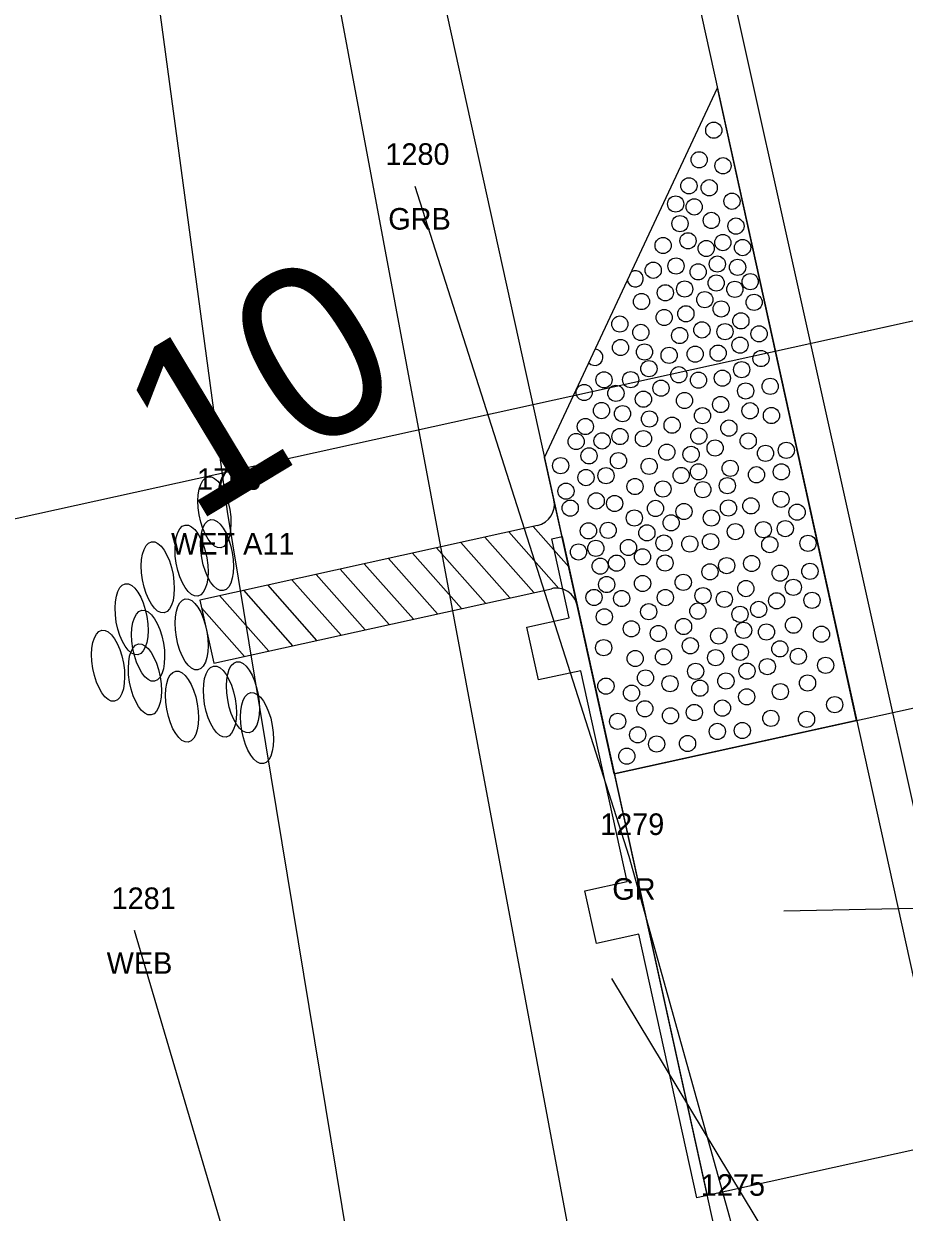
# Model space of a CAD drawing. Extents: x 2522090 to 2524658, y 882711 to 887512.
# Drawn here: x 2523721.1 to 2523761.9, y 885177.3 to 885232.4 of the extents above; entities that cross this region are included whole.
import ezdxf

# ---------------------------------------------------------------- set-up
doc = ezdxf.new("R2010")
doc.units = 0
for name, color, linetype in [('RD_EV_JurisArea', 7, 'Continuous'), ('RD_EX_GuardRail', 7, 'Continuous'), ('RD_EX_GuardRail_txCode', 7, 'Continuous'), ('RD_EX_H2O', 7, 'Continuous'), ('RD_EX_H2O_txCode', 7, 'Continuous'), ('RD_EX_H2O_WetLd_txCode', 7, 'Continuous'), ('RD_EX_Road', 7, 'Continuous'), ('RD_EX_VEG', 7, 'Continuous'), ('RD_HC_Data_Tic', 7, 'Continuous'), ('RD_HC_TX_Sta50', 7, 'Continuous'), ('RD_PD_Bridge', 7, 'Continuous'), ('RD_PD_Final_TrvlWay', 7, 'Continuous'), ('RD_PD_GR', 7, 'Continuous'), ('RD_PD_PatLn5', 7, 'Continuous'), ('RD_PD_PatLn6', 7, 'Continuous'), ('RD_PD_PaveShd', 7, 'Continuous'), ('RD_SMD_Locator', 7, 'Continuous')]:
    doc.layers.add(name, color=color, linetype=linetype)

# ---------------------------------------------------------------- blocks, each defined once
blk = doc.blocks.new('TBC1')
at = {"layer": 'RD_PD_GR'}
blk.add_lwpolyline([(12.5, 2.5), (15, 2.5), (15, 0.492), (25, 0.492), (25, 2.5), (27.5, 2.5), (27.5, 0.492), (31.25, 0.492), (31.25, 0), (0, 0), (0, 0.492), (12.5, 0.492)], close=True, dxfattribs=at)

msp = doc.modelspace()

# ---------------------------------------------------------------- linework, layer by layer
at = {"layer": 'RD_EV_JurisArea'}
msp.add_lwpolyline([(2523761.167, 885134.03), (2523740.577, 885149.032), (2523730.546, 885209.774), (2523710.597, 885357.475), (2523698.092, 885411.187), (2523674.928, 885498.624), (2523657.597, 885564.237), (2523640.817, 885610.871), (2523583.661, 885726.913), (2523539.208, 885693.17), (2523494.424, 885646.975)], dxfattribs=at)
at = {"layer": 'RD_EX_GuardRail'}
msp.add_lwpolyline([(2523760.648, 885150.236), (2523753.83, 885177.075), (2523749.161, 885193.784), (2523739.251, 885224.823)], dxfattribs=at)
at = {"layer": 'RD_EX_H2O'}
msp.add_line((2523738.909, 885147.498), (2523726.241, 885190.354), dxfattribs=at)
at = {"layer": 'RD_EX_Road'}
msp.add_line((2523771.576, 885154.562), (2523750.317, 885250.176), dxfattribs=at)
at = {"layer": 'RD_EX_VEG'}
msp.add_lwpolyline([(2523749.808, 885158.06), (2523732.862, 885248.57), (2523691.618, 885438.948), (2523639.516, 885601.035)], dxfattribs=at)
at = {"layer": 'RD_HC_Data_Tic'}
msp.add_line((2523767.659, 885219.76), (2523759.846, 885218.04), dxfattribs=at)
at = {"layer": 'RD_PD_Bridge'}
msp.add_line((2523748.471, 885197.618), (2523794.372, 885207.726), dxfattribs=at)
for points in [[(2523748.471, 885197.618), (2523785.03, 885031.596)], [(2523798.673, 885188.194), (2523752.772, 885178.086)]]:
    msp.add_lwpolyline(points, dxfattribs=at)
at = {"layer": 'RD_PD_Final_TrvlWay'}
msp.add_line((2523698.951, 885475.979), (2524014, 884045.256), dxfattribs=at)
at = {"layer": 'RD_PD_GR'}
msp.add_line((2523746.052, 885208.605), (2523684.387, 885488.643), dxfattribs=at)
at = {"layer": 'RD_PD_PatLn5'}
msp.add_line((2523845.787, 885236.964), (2523689.531, 885202.556), dxfattribs=at)
at = {"layer": 'RD_PD_PatLn6'}
for p, q in [((2523756.322, 885191.277), (2523916.292, 885194.412)), ((2523748.348, 885188.144), (2523831.037, 885051.167))]:
    msp.add_line(p, q, dxfattribs=at)
at = {"layer": 'RD_PD_PaveShd'}
for p, q in [((2523745.246, 885212.267), (2523753.251, 885229.39)), ((2523759.702, 885200.091), (2523753.251, 885229.39)), ((2523745.891, 885209.338), (2523745.246, 885212.267)), ((2523746.536, 885206.408), (2523745.891, 885209.338)), ((2523744.915, 885209.122), (2523729.268, 885205.668)), ((2523745.91, 885206.206), (2523743.589, 885208.829)), ((2523746.36, 885207.207), (2523744.706, 885209.076)), ((2523743.629, 885205.766), (2523741.355, 885208.336)), ((2523743.629, 885205.766), (2523741.355, 885208.336)), ((2523744.746, 885206.013), (2523742.472, 885208.583)), ((2523744.746, 885206.013), (2523742.472, 885208.583)), ((2523741.395, 885205.273), (2523739.121, 885207.843)), ((2523741.395, 885205.273), (2523739.121, 885207.843)), ((2523742.512, 885205.519), (2523740.238, 885208.09)), ((2523742.512, 885205.519), (2523740.238, 885208.09)), ((2523738.044, 885204.533), (2523735.77, 885207.103)), ((2523738.044, 885204.533), (2523735.77, 885207.103)), ((2523739.161, 885204.78), (2523736.887, 885207.35)), ((2523739.161, 885204.78), (2523736.887, 885207.35)), ((2523740.278, 885205.026), (2523738.004, 885207.597)), ((2523740.278, 885205.026), (2523738.004, 885207.597)), ((2523746.322, 885207.379), (2523746.322, 885207.379)), ((2523735.81, 885204.04), (2523733.536, 885206.61)), ((2523735.81, 885204.04), (2523733.536, 885206.61)), ((2523736.927, 885204.287), (2523734.653, 885206.857)), ((2523736.927, 885204.287), (2523734.653, 885206.857)), ((2523729.915, 885202.739), (2523745.559, 885206.192)), ((2523733.576, 885203.547), (2523731.302, 885206.117)), ((2523733.576, 885203.547), (2523731.302, 885206.117)), ((2523734.693, 885203.793), (2523732.419, 885206.364)), ((2523734.693, 885203.793), (2523732.419, 885206.364)), ((2523746.536, 885206.408), (2523748.471, 885197.618)), ((2523748.471, 885197.618), (2523746.536, 885206.408)), ((2523729.268, 885205.668), (2523729.915, 885202.739)), ((2523729.268, 885205.668), (2523729.915, 885202.739)), ((2523732.459, 885203.3), (2523730.185, 885205.871)), ((2523732.459, 885203.3), (2523730.185, 885205.871)), ((2523731.342, 885203.054), (2523729.348, 885205.307)), ((2523731.342, 885203.054), (2523729.348, 885205.307)), ((2523759.702, 885200.091), (2523748.471, 885197.618))]:
    msp.add_line(p, q, dxfattribs=at)
for centre in [(2523753.083, 885227.427), (2523753.083, 885227.427), (2523752.405, 885226.058), (2523752.405, 885226.058), (2523753.511, 885225.782), (2523753.511, 885225.782), (2523751.931, 885224.852), (2523751.931, 885224.852), (2523752.872, 885224.763), (2523752.872, 885224.763), (2523751.317, 885224.011), (2523752.176, 885223.875), (2523752.176, 885223.875), (2523753.924, 885224.137), (2523753.924, 885224.137), (2523752.971, 885223.25), (2523752.971, 885223.25), (2523751.517, 885223.101), (2523754.11, 885222.987), (2523754.11, 885222.987), (2523751.887, 885222.306), (2523751.887, 885222.306), (2523753.502, 885222.223), (2523753.502, 885222.223), (2523750.735, 885222.088), (2523750.735, 885222.088), (2523752.732, 885221.95), (2523752.732, 885221.95), (2523754.418, 885221.991), (2523754.418, 885221.991), (2523751.334, 885221.137), (2523751.334, 885221.137), (2523753.249, 885221.228), (2523753.249, 885221.228), (2523754.186, 885221.075), (2523754.186, 885221.075), (2523750.277, 885220.942), (2523750.277, 885220.942), (2523752.36, 885220.866), (2523752.36, 885220.866), (2523751.734, 885220.071), (2523751.734, 885220.071), (2523753.195, 885220.35), (2523753.195, 885220.35), (2523754.059, 885220.057), (2523754.059, 885220.057), (2523754.771, 885220.414), (2523754.771, 885220.414), (2523749.734, 885219.491), (2523749.734, 885219.491), (2523750.839, 885219.898), (2523750.839, 885219.898), (2523752.667, 885219.581), (2523752.667, 885219.581), (2523754.953, 885219.457), (2523754.953, 885219.457), (2523751.79, 885218.926), (2523751.79, 885218.926), (2523753.426, 885219.149), (2523753.426, 885219.149), (2523748.73, 885218.449), (2523750.784, 885218.753), (2523750.784, 885218.753), (2523754.339, 885218.596), (2523754.339, 885218.596), (2523749.703, 885218.062), (2523749.703, 885218.062), (2523751.504, 885217.917), (2523751.504, 885217.917), (2523752.533, 885218.178), (2523752.533, 885218.178), (2523753.603, 885218.096), (2523753.603, 885218.096), (2523755.182, 885217.997), (2523755.182, 885217.997), (2523748.762, 885217.362), (2523748.762, 885217.362), (2523754.3, 885217.473), (2523754.3, 885217.473), (2523749.872, 885217.154), (2523749.872, 885217.154), (2523751.013, 885217), (2523751.013, 885217), (2523752.221, 885217.056), (2523752.221, 885217.056), (2523753.283, 885217.103), (2523753.283, 885217.103), (2523755.271, 885216.851), (2523755.271, 885216.851), (2523750.077, 885216.383), (2523750.077, 885216.383), (2523751.464, 885216.102), (2523751.464, 885216.102), (2523754.376, 885216.338), (2523754.376, 885216.338), (2523747.996, 885215.865), (2523747.996, 885215.865), (2523749.232, 885215.874), (2523749.232, 885215.874), (2523752.374, 885215.85), (2523752.374, 885215.85), (2523753.482, 885215.944), (2523753.482, 885215.944), (2523755.697, 885215.563), (2523755.697, 885215.563), (2523747.077, 885215.279), (2523748.548, 885215.242), (2523748.548, 885215.242), (2523749.822, 885214.968), (2523749.822, 885214.968), (2523750.639, 885215.479), (2523750.639, 885215.479), (2523754.561, 885215.351), (2523754.561, 885215.351), (2523747.881, 885214.441), (2523747.881, 885214.441), (2523751.727, 885214.908), (2523751.727, 885214.908), (2523753.4, 885214.721), (2523753.4, 885214.721), (2523754.765, 885214.434), (2523754.765, 885214.434), (2523748.855, 885214.298), (2523748.855, 885214.298), (2523750.103, 885214.053), (2523750.103, 885214.053), (2523752.561, 885214.204), (2523752.561, 885214.204), (2523755.755, 885214.212), (2523755.755, 885214.212), (2523747.134, 885213.702), (2523747.134, 885213.702), (2523751.152, 885213.764), (2523751.152, 885213.764), (2523753.783, 885213.631), (2523753.783, 885213.631), (2523746.705, 885213.009), (2523747.907, 885213.037), (2523747.907, 885213.037), (2523748.734, 885213.239), (2523748.734, 885213.239), (2523749.823, 885213.144), (2523749.823, 885213.144), (2523752.391, 885213.261), (2523752.391, 885213.261), (2523754.679, 885213.036), (2523754.679, 885213.036), (2523747.304, 885212.344), (2523747.304, 885212.344), (2523747.304, 885212.344), (2523750.907, 885212.517), (2523750.907, 885212.517), (2523752.031, 885212.413), (2523752.031, 885212.413), (2523753.144, 885212.71), (2523753.144, 885212.71), (2523755.479, 885212.461), (2523755.479, 885212.461), (2523756.442, 885212.599), (2523756.442, 885212.599), (2523745.985, 885211.892), (2523745.985, 885211.892), (2523748.665, 885212.121), (2523748.665, 885212.121), (2523750.088, 885211.858), (2523750.088, 885211.858), (2523753.844, 885211.769), (2523753.844, 885211.769), (2523747.159, 885211.339), (2523747.159, 885211.339), (2523748.09, 885211.426), (2523748.09, 885211.426), (2523751.571, 885211.438), (2523751.571, 885211.438), (2523752.374, 885211.606), (2523752.374, 885211.606), (2523755.061, 885211.47), (2523755.061, 885211.47), (2523756.213, 885211.603), (2523756.213, 885211.603), (2523746.232, 885210.709), (2523746.232, 885210.709), (2523749.434, 885210.923), (2523749.434, 885210.923), (2523750.726, 885210.809), (2523750.726, 885210.809), (2523752.576, 885210.78), (2523752.576, 885210.78), (2523753.711, 885210.963), (2523753.711, 885210.963), (2523747.636, 885210.258), (2523747.636, 885210.258), (2523748.488, 885210.139), (2523748.488, 885210.139), (2523754.804, 885210.027), (2523754.804, 885210.027), (2523756.198, 885210.334), (2523756.198, 885210.334), (2523746.431, 885209.925), (2523746.431, 885209.925), (2523749.401, 885209.466), (2523749.401, 885209.466), (2523750.383, 885209.911), (2523750.383, 885209.911), (2523751.7, 885209.768), (2523751.7, 885209.768), (2523752.973, 885209.465), (2523752.973, 885209.465), (2523753.762, 885209.928), (2523753.762, 885209.928), (2523756.943, 885209.736), (2523751.107, 885209.243), (2523751.107, 885209.243), (2523755.382, 885208.925), (2523755.382, 885208.925), (2523756.396, 885208.975), (2523756.396, 885208.975), (2523747.274, 885208.869), (2523747.274, 885208.869), (2523748.187, 885208.895), (2523748.187, 885208.895), (2523749.984, 885208.778), (2523749.984, 885208.778), (2523752.935, 885208.373), (2523752.935, 885208.373), (2523754.086, 885208.836), (2523754.086, 885208.836), (2523746.815, 885207.894), (2523746.815, 885207.894), (2523747.618, 885208.062), (2523747.618, 885208.062), (2523749.128, 885208.101), (2523749.128, 885208.101), (2523750.774, 885208.306), (2523750.774, 885208.306), (2523751.973, 885208.264), (2523751.973, 885208.264), (2523755.677, 885208.234), (2523755.677, 885208.234), (2523757.449, 885208.294), (2523757.449, 885208.294), (2523748.579, 885207.377), (2523748.579, 885207.377), (2523749.781, 885207.665), (2523749.781, 885207.665), (2523750.825, 885207.38), (2523750.825, 885207.38), (2523753.681, 885207.261), (2523753.681, 885207.261), (2523754.837, 885207.359), (2523754.837, 885207.359), (2523747.82, 885207.236), (2523747.82, 885207.236), (2523752.905, 885206.972), (2523752.905, 885206.972), (2523756.158, 885206.913), (2523756.158, 885206.913), (2523757.538, 885206.997), (2523757.538, 885206.997), (2523748.12, 885206.384), (2523749.784, 885206.434), (2523749.784, 885206.434), (2523751.668, 885206.487), (2523751.668, 885206.487), (2523754.57, 885206.197), (2523754.57, 885206.197), (2523756.768, 885206.256), (2523756.768, 885206.256), (2523747.535, 885205.787), (2523747.535, 885205.787), (2523748.815, 885205.735), (2523748.815, 885205.735), (2523750.839, 885205.78), (2523750.839, 885205.78), (2523752.585, 885205.869), (2523752.585, 885205.869), (2523753.571, 885205.701), (2523753.571, 885205.701), (2523755.995, 885205.633), (2523755.995, 885205.633), (2523757.635, 885205.655), (2523757.635, 885205.655), (2523750.069, 885205.126), (2523750.069, 885205.126), (2523752.345, 885205.155), (2523752.345, 885205.155), (2523755.162, 885205.232), (2523755.162, 885205.232), (2523748.013, 885204.888), (2523748.013, 885204.888), (2523754.3, 885205.007), (2523754.3, 885205.007), (2523749.263, 885204.333), (2523749.263, 885204.333), (2523750.513, 885204.116), (2523750.513, 885204.116), (2523751.683, 885204.438), (2523751.683, 885204.438), (2523753.313, 885204.001), (2523753.313, 885204.001), (2523754.464, 885204.264), (2523755.524, 885204.185), (2523755.524, 885204.185), (2523756.778, 885204.501), (2523756.778, 885204.501), (2523758.072, 885204.085), (2523758.072, 885204.085), (2523747.982, 885203.459), (2523747.982, 885203.459), (2523751.994, 885203.549), (2523751.994, 885203.549), (2523749.442, 885202.958), (2523749.442, 885202.958), (2523750.755, 885203.035), (2523750.755, 885203.035), (2523753.168, 885202.996), (2523753.168, 885202.996), (2523754.316, 885203.249), (2523754.316, 885203.249), (2523756.145, 885203.404), (2523756.145, 885203.404), (2523756.999, 885203.057), (2523756.999, 885203.057), (2523752.241, 885202.366), (2523752.241, 885202.366), (2523754.622, 885202.375), (2523754.622, 885202.375), (2523755.566, 885202.583), (2523755.566, 885202.583), (2523758.265, 885202.642), (2523758.265, 885202.642), (2523749.92, 885202.059), (2523749.92, 885202.059), (2523751.055, 885201.793), (2523751.055, 885201.793), (2523753.645, 885201.915), (2523753.645, 885201.915), (2523757.429, 885201.824), (2523757.429, 885201.824), (2523748.085, 885201.68), (2523748.085, 885201.68), (2523749.272, 885201.355), (2523749.272, 885201.355), (2523752.44, 885201.582), (2523752.44, 885201.582), (2523756.169, 885201.424), (2523756.169, 885201.424), (2523753.484, 885200.662), (2523753.484, 885200.662), (2523754.61, 885201.183), (2523754.61, 885201.183), (2523758.687, 885200.821), (2523758.687, 885200.821), (2523749.889, 885200.63), (2523749.889, 885200.63), (2523751.076, 885200.305), (2523751.076, 885200.305), (2523752.18, 885200.461), (2523752.18, 885200.461), (2523755.728, 885200.188), (2523755.728, 885200.188), (2523757.382, 885200.143), (2523757.382, 885200.143), (2523748.63, 885200.047), (2523748.63, 885200.047), (2523753.249, 885199.582), (2523753.249, 885199.582), (2523754.403, 885199.624), (2523754.403, 885199.624), (2523749.557, 885199.423), (2523751.868, 885199.022), (2523751.868, 885199.022), (2523750.434, 885198.997), (2523750.434, 885198.997), (2523750.434, 885198.997), (2523749.053, 885198.436), (2523749.053, 885198.436)]:
    msp.add_circle(centre, 0.375, dxfattribs=at)
for centre, radius, start, end in [((2523749.446, 885220.543), 0.375, 191.7998, 118.0848), ((2523747.57, 885216.908), 0.375, 222.987, 86.8976), ((2523744.699, 885210.099), 1, 282.4481, 12.4185), ((2523745.775, 885205.216), 1, 12.4185, 102.4481)]:
    msp.add_arc(centre, radius, start, end, dxfattribs=at)
for centre in [(2523729.946, 885209.731), (2523730.062, 885207.747), (2523728.882, 885207.495), (2523728.882, 885207.495), (2523727.319, 885206.721), (2523727.319, 885206.721), (2523726.104, 885204.775), (2523726.104, 885204.775), (2523728.885, 885204.078), (2523728.885, 885204.078), (2523726.872, 885203.55), (2523726.872, 885203.55), (2523725.018, 885202.625), (2523725.018, 885202.625), (2523726.72, 885201.988), (2523726.72, 885201.988), (2523731.264, 885201.164), (2523731.264, 885201.164), (2523728.441, 885200.732), (2523728.441, 885200.732), (2523730.196, 885200.962), (2523730.196, 885200.962), (2523731.918, 885199.734), (2523731.918, 885199.734)]:
    msp.add_ellipse(centre, major_axis=(-0.292, 1.645), ratio=0.429445, dxfattribs=at)
at = {"layer": 'RD_SMD_Locator'}
for centre in [(2523739.251, 885224.823), (2523730.546, 885209.774), (2523749.161, 885193.784), (2523726.241, 885190.354)]:
    msp.add_circle(centre, 0.001, dxfattribs=at)

# ---------------------------------------------------------------- block references
at = {"layer": 'RD_PD_Bridge', "rotation": 102.41848259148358}
msp.add_blockref('TBC1', (2523752.772, 885178.086), dxfattribs=at)

# ---------------------------------------------------------------- texts
at = {"layer": 'RD_EX_GuardRail_txCode'}
for s, p in [('1280', (2523737.865, 885225.823)), ('GRB', (2523737.999, 885222.823)), ('1279', (2523747.814, 885194.784)), ('GR', (2523748.381, 885191.784)), ('1275', (2523752.484, 885178.075))]:
    msp.add_text(s, height=1, dxfattribs=at).set_placement(p)
at = {"layer": 'RD_EX_H2O_txCode'}
for s, p in [('1281', (2523725.178, 885191.354)), ('WEB', (2523724.949, 885188.354))]:
    msp.add_text(s, height=1, dxfattribs=at).set_placement(p)
at = {"layer": 'RD_EX_H2O_WetLd_txCode'}
for s, p in [('1706', (2523729.137, 885210.774)), ('WET A11', (2523727.932, 885207.774))]:
    msp.add_text(s, height=1, dxfattribs=at).set_placement(p)
at = {"layer": 'RD_HC_TX_Sta50'}
msp.add_text('10', height=8, rotation=31.1184, dxfattribs=at).set_placement((2523728.916, 885209.119))

doc.saveas('drawing.dxf')
